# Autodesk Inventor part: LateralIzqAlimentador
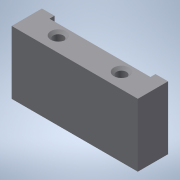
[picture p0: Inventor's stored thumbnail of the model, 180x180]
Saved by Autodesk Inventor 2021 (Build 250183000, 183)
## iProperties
Created: 2021-02
Part Number: LateralIzqAlimentador
Material: Genérico
Document SubType Name: Modeling
Designer: ATOUZA
Density: 1 g/cm^3
Appearance: Valor por defecto
Author: ATOUZA
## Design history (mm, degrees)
node "Plano de trabajo1"
sketch "Boceto1"
  geometry: L1 (-20, 18)-(20, 18) reference; L2 (20, 20)-(20, 18) reference; L3 (-20, 20)-(20, 20) reference; L4 (-20, 18)-(-20, 20) reference; L5 (20, 20)-(-20, 20); L6 (25, 30)-(-25, 30); L7 (-25, 30)-(-25, 18); L8 (-25, 18)-(-20, 18); L9 (-20, 18)-(-20, 20); L10 (25, 30)-(25, 18); L11 (25, 18)-(20, 18); L12 (20, 18)-(20, 20); 1 further point
  constraints: 16 end point, 3 parallel, 2 horizontal, 2 point on line, 1 perpendicular
  dimensions: "d1" = 5 distance of L8.end L7.end; "d2" = 5 distance of L10.end L11.end; "d3" = 12 distance of L6.start L10.end; "d4" = 50 distance of L6.start L6.end
extrude "Extrusión1" new body sketch "Boceto1" distance "d5" = 25; taper "d6" = 0 deg
sketch "Boceto2"
  geometry: L1 (-25, -18)-(-25, -30) reference; L2 (-25, -24)-(0, -24); L3 (0, -24)-(25, -24); L4 (25, -30)-(25, -18) reference; C1 r 2 at (12.5, -24); C2 r 2 at (-12.5, -24)
  constraints: 4 end point, 4 midpoint, 2 centre point, 1 horizontal
  dimensions: "d7" = 4 diameter of C1; "d8" = 4 diameter of C2
hole "Agujero1" sketch "Boceto2" at (-12.5, -24), (12.5, -24) diameter "d9" = 4; stored, may be unused: countersink angle "d13" = 90 deg, drill point angle "d15" = 118 deg; dims "d10" = 6, "d11" = 6, "d12" = 2, "d14" = 8
node "Sólido1"
node "Referencia1"
